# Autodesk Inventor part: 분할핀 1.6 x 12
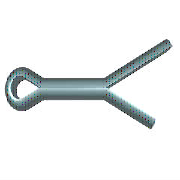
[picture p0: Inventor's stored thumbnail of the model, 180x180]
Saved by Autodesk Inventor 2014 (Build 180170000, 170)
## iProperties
IsCustomPart: 1
Created: 2012-02
Part Number: 분할핀 1.6 x 12
Material: 강철, 연강
Description: 분할 핀
Document SubType Name: Modeling
Standard: KS B 1321
Designer: mduedu
Standards Organization: KS
Language: ko-KR
Size Designation: 1.6 x  12
Categories: <MemberInstance><Categories><Category DisplayName="조임쇠" InternalName="e4da775c-781d-43d5-af7c-5136215cf5a6" Mnemonic="FSTN"><Category DisplayName="핀" InternalNa
Density: 1 g/cm^3
Appearance: Steel
Author: mduedu
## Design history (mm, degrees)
sketch "스케치1"
  geometry: L1 (0, 0.7)-(7, 0.7); L2 (0, -0.7)-(7, -0.7); L3 (7, 0.7)-(12, 2.616); L4 (12, 2.616)-(12.234, 2.005); L5 (12.234, 2.005)-(7, 0); L6 (7, 0)-(14.734, -2.963); L7 (14.734, -2.963)-(14.5, -3.573); L8 (14.5, -3.573)-(7, -0.7); L9 (0, 0)-(-1.528, -0.645); L10 (0, 0)-(-1.528, 0.645); L11 (0, 0.7)-(0, -0.7); L12 (0, 0.7)-(-1.204, 1.267); L13 (0, -0.7)-(-1.204, -1.267); L14 (-3.2, 0)-(7, 0); L15 (7, 0.7)-(7, -0.7); A1 r 1.4 centre (-1.8, 0) between (-1.204, 1.267) and (-1.204, -1.267); A2 r 0.7 centre (-1.8, 0) between (-1.528, 0.645) and (-1.528, -0.645); 1 further point
  constraints: 30 end point, 5 point on circle, 4 parallel, 4 perpendicular, 4 point on line, 4 tangent, 2 centre point, 2 midpoint, 1 coincident, 1 horizontal
  dimensions: "d0" = 7 distance of L1.start L1.end (= MSIAB); "d1" = 12 horizontal distance of L1.start L3.end (= SNLG); "d2" = 159.037 deg angle of L1 L3; "d3" = 159.037 deg angle of L2 L8; "d4" = 2.5 horizontal distance of L3.end L7.end (= LGDIF); "d5" = 0.7 radius of A2 (= -0.5 x SNND1 + 0.5 x KBR); "d6" = 1.4 radius of A1 (= 0.5 x KBR); "d7" = 0.7 distance from line of L1 L9.start (= 0.5 x SNND1); "d8" = 0.7 distance between parallel lines of L2 L14 (= 0.5 x SNND1); "d9" = 1.8 distance from line of L11 A1.centre (= KOL - 0.5 x KBR)
extrude "본체" new body sketch "스케치1" stored distance "d10" = 1.4 (= SNND1); taper "d11" = 0 deg
workaxis "Work Axis1"
workplane "Work Plane1"
body "Solid1"
fillet "모깎기" dims "d12" = 0.49 (= 0.35 x SNND1)
workplane "Work Plane3"
other parameters: "SNND" = 1.6 [user parameter], "SNLG" = 12 [user parameter; used in 1 equation term], "SNND1" = 1.4 [user parameter; used in 5 equation terms], "KBR" = 2.8 [user parameter; used in 3 equation terms], "KOL" = 3.2 [user parameter; used in 1 equation term], "LGDIF" = 2.5 [user parameter; used in 1 equation term], "MSIAB" = 7 [user parameter; used in 1 equation term], "d15" = 0, "d16" = 0, "d17" = 0, "NNDMAX" = 7 [user parameter], "DSH" = 6 [user parameter], "NNDMIN" = 5.5 [user parameter]
